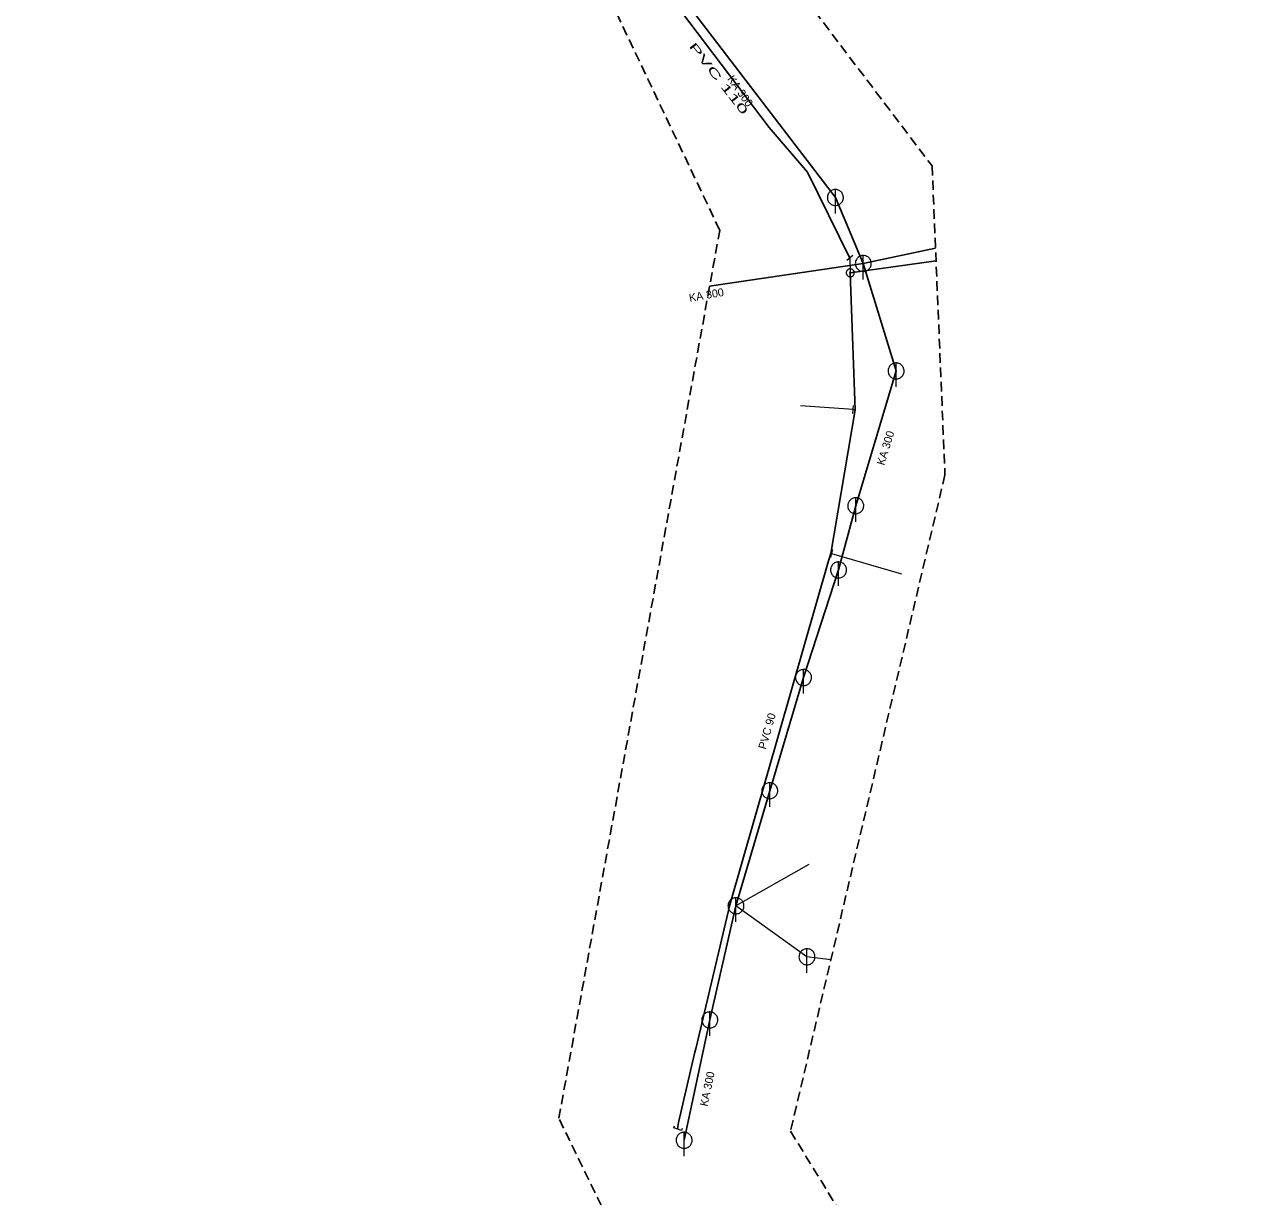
# Model space of a CAD drawing. Extents: x -686636 to -686482, y -972667 to -972167.
# Drawn here: x -686636.4 to -686482.1, y -972450.3 to -972304 of the extents above; entities that cross this region are included whole.
import ezdxf

# ---------------------------------------------------------------- set-up
doc = ezdxf.new("R2010")
doc.units = 0
doc.header["$LTSCALE"] = 0.4
doc.linetypes.add('MEDIUM_DASHED', pattern=[4.5, 3, -1.5])
for name, color, linetype, lineweight in [('1', 7, 'MEDIUM_DASHED', 25), ('11', 7, 'Continuous', 13), ('13', 7, 'Continuous', 13), ('14', 7, 'Continuous', 25), ('17', 7, 'Continuous', 25), ('22', 7, 'Continuous', 13), ('34', 7, 'Continuous', 13), ('47', 7, 'Continuous', 13)]:
    doc.layers.add(name, color=color, linetype=linetype, lineweight=lineweight)

msp = doc.modelspace()

# ---------------------------------------------------------------- linework, layer by layer
at = {"layer": '1'}
msp.add_lwpolyline([(-686523.086, -972200.227), (-686492.539, -972167.269), (-686482.089, -972185.758), (-686542.379, -972270.164), (-686548.006, -972279.81), (-686543.183, -972295.084), (-686523.086, -972321.612), (-686521.478, -972360.197), (-686540.771, -972442.192), (-686521.478, -972473.543), (-686515.047, -972510.521), (-686519.067, -972578.85), (-686529.517, -972667.276), (-686549.614, -972665.668), (-686542.379, -972574.831), (-686589.003, -972562.773), (-686636.432, -972544.284), (-686625.981, -972525.795), (-686541.575, -972549.911), (-686539.967, -972501.678), (-686569.711, -972440.584), (-686549.614, -972329.65), (-686564.887, -972297.496), (-686572.926, -972277.399)], close=True, dxfattribs=at)
at = {"layer": '11'}
msp.add_line((-686538.49, -972408.895), (-686547.583, -972414.038), dxfattribs=at)
msp.add_lwpolyline([(-686535.737, -972420.795), (-686538.713, -972420.403), (-686547.583, -972414.038)], dxfattribs=at)
at = {"layer": '13'}
for p, q in [((-686532.934, -972352.037), (-686539.513, -972351.594)), ((-686535.644, -972370.026), (-686526.917, -972372.571))]:
    msp.add_line(p, q, dxfattribs=at)
at = {"layer": '14'}
for p, q in [((-686554.905, -972299.7), (-686535.172, -972325.548)), ((-686535.172, -972325.548), (-686531.678, -972333.79)), ((-686522.659, -972331.868), (-686531.678, -972333.79)), ((-686531.678, -972333.79), (-686550.876, -972336.617)), ((-686527.584, -972347.218), (-686531.678, -972333.79)), ((-686532.626, -972364.055), (-686527.584, -972347.218)), ((-686534.77, -972372.079), (-686532.626, -972364.055)), ((-686539.147, -972385.523), (-686534.77, -972372.079)), ((-686543.365, -972399.661), (-686539.147, -972385.523)), ((-686547.583, -972414.038), (-686543.365, -972399.661)), ((-686550.85, -972428.295), (-686547.583, -972414.038)), ((-686554.058, -972443.325), (-686550.85, -972428.295))]:
    msp.add_line(p, q, dxfattribs=at)
at = {"layer": '14', "lineweight": 13}
for p, q in [((-686533.358, -972333.116), (-686533.307, -972334.963)), ((-686532.708, -972352.056), (-686532.934, -972352.037)), ((-686535.729, -972370.005), (-686535.644, -972370.026))]:
    msp.add_line(p, q, dxfattribs=at)
at = {"layer": '17'}
msp.add_line((-686533.307, -972334.963), (-686522.593, -972333.453), dxfattribs=at)
for points in [[(-686556.579, -972299.256), (-686556.334, -972299.737), (-686543.419, -972316.782), (-686538.645, -972322.384), (-686533.358, -972333.116)], [(-686533.307, -972334.963), (-686532.708, -972352.056), (-686535.729, -972370.005), (-686536.037, -972370.929), (-686548.355, -972413.919), (-686552.556, -972431.757), (-686552.713, -972432.325), (-686554.769, -972441.1), (-686554.808, -972441.374), (-686554.848, -972441.648), (-686554.867, -972441.942)]]:
    msp.add_lwpolyline(points, dxfattribs=at)
at = {"layer": '22'}
for p, q in [((-686535.172, -972327.548), (-686535.171, -972324.548)), ((-686531.678, -972335.79), (-686531.677, -972332.79)), ((-686527.584, -972349.218), (-686527.583, -972346.218)), ((-686532.626, -972366.055), (-686532.625, -972363.055)), ((-686534.77, -972374.079), (-686534.769, -972371.079)), ((-686539.147, -972387.523), (-686539.146, -972384.523)), ((-686543.365, -972401.661), (-686543.364, -972398.661)), ((-686547.583, -972416.038), (-686547.582, -972413.038)), ((-686538.713, -972422.403), (-686538.712, -972419.403)), ((-686550.85, -972430.295), (-686550.849, -972427.295)), ((-686554.058, -972445.325), (-686554.057, -972442.325))]:
    msp.add_line(p, q, dxfattribs=at)
for points in [[(-686534.172, -972325.548), (-686534.177, -972325.439), (-686534.195, -972325.331), (-686534.225, -972325.225), (-686534.265, -972325.124), (-686534.317, -972325.027), (-686534.379, -972324.937), (-686534.451, -972324.854), (-686534.531, -972324.78), (-686534.619, -972324.714), (-686534.713, -972324.659), (-686534.813, -972324.614), (-686534.918, -972324.581), (-686535.025, -972324.559), (-686535.134, -972324.549), (-686535.244, -972324.551), (-686535.352, -972324.565), (-686535.459, -972324.59), (-686535.562, -972324.627), (-686535.66, -972324.676), (-686535.752, -972324.734), (-686535.838, -972324.803), (-686535.915, -972324.88), (-686535.984, -972324.966), (-686536.043, -972325.058), (-686536.091, -972325.156), (-686536.128, -972325.259), (-686536.154, -972325.366), (-686536.168, -972325.474), (-686536.171, -972325.584), (-686536.161, -972325.693), (-686536.14, -972325.8), (-686536.106, -972325.904), (-686536.062, -972326.004), (-686536.007, -972326.099), (-686535.941, -972326.187), (-686535.867, -972326.267), (-686535.784, -972326.339), (-686535.694, -972326.401), (-686535.598, -972326.453), (-686535.496, -972326.494), (-686535.391, -972326.524), (-686535.283, -972326.542), (-686535.173, -972326.548), (-686535.064, -972326.542), (-686534.956, -972326.524), (-686534.851, -972326.495), (-686534.749, -972326.454), (-686534.652, -972326.402), (-686534.562, -972326.34), (-686534.479, -972326.269), (-686534.404, -972326.189), (-686534.339, -972326.101), (-686534.283, -972326.007), (-686534.239, -972325.907), (-686534.205, -972325.803), (-686534.183, -972325.695), (-686534.173, -972325.586)], [(-686530.678, -972333.79), (-686530.683, -972333.681), (-686530.701, -972333.573), (-686530.731, -972333.467), (-686530.771, -972333.366), (-686530.823, -972333.269), (-686530.885, -972333.179), (-686530.957, -972333.096), (-686531.037, -972333.022), (-686531.125, -972332.956), (-686531.219, -972332.901), (-686531.319, -972332.856), (-686531.424, -972332.823), (-686531.531, -972332.801), (-686531.64, -972332.791), (-686531.75, -972332.793), (-686531.858, -972332.807), (-686531.965, -972332.832), (-686532.068, -972332.869), (-686532.166, -972332.918), (-686532.258, -972332.976), (-686532.344, -972333.045), (-686532.421, -972333.122), (-686532.49, -972333.208), (-686532.549, -972333.3), (-686532.597, -972333.398), (-686532.634, -972333.501), (-686532.66, -972333.608), (-686532.674, -972333.716), (-686532.677, -972333.826), (-686532.667, -972333.935), (-686532.646, -972334.042), (-686532.612, -972334.146), (-686532.568, -972334.246), (-686532.513, -972334.341), (-686532.447, -972334.429), (-686532.373, -972334.509), (-686532.29, -972334.581), (-686532.2, -972334.643), (-686532.104, -972334.695), (-686532.002, -972334.736), (-686531.897, -972334.766), (-686531.789, -972334.784), (-686531.679, -972334.79), (-686531.57, -972334.784), (-686531.462, -972334.766), (-686531.357, -972334.737), (-686531.255, -972334.696), (-686531.158, -972334.644), (-686531.068, -972334.582), (-686530.985, -972334.511), (-686530.91, -972334.431), (-686530.845, -972334.343), (-686530.789, -972334.249), (-686530.745, -972334.149), (-686530.711, -972334.045), (-686530.689, -972333.937), (-686530.679, -972333.828)], [(-686526.584, -972347.218), (-686526.589, -972347.109), (-686526.607, -972347.001), (-686526.637, -972346.895), (-686526.677, -972346.794), (-686526.729, -972346.697), (-686526.791, -972346.607), (-686526.863, -972346.524), (-686526.943, -972346.45), (-686527.031, -972346.384), (-686527.125, -972346.329), (-686527.225, -972346.284), (-686527.33, -972346.251), (-686527.437, -972346.229), (-686527.546, -972346.219), (-686527.656, -972346.221), (-686527.764, -972346.235), (-686527.871, -972346.26), (-686527.974, -972346.297), (-686528.072, -972346.346), (-686528.164, -972346.404), (-686528.25, -972346.473), (-686528.327, -972346.55), (-686528.396, -972346.636), (-686528.455, -972346.728), (-686528.503, -972346.826), (-686528.54, -972346.929), (-686528.566, -972347.036), (-686528.58, -972347.144), (-686528.583, -972347.254), (-686528.573, -972347.363), (-686528.552, -972347.47), (-686528.518, -972347.574), (-686528.474, -972347.674), (-686528.419, -972347.769), (-686528.353, -972347.857), (-686528.279, -972347.937), (-686528.196, -972348.009), (-686528.106, -972348.071), (-686528.01, -972348.123), (-686527.908, -972348.164), (-686527.803, -972348.194), (-686527.695, -972348.212), (-686527.585, -972348.218), (-686527.476, -972348.212), (-686527.368, -972348.194), (-686527.263, -972348.165), (-686527.161, -972348.124), (-686527.064, -972348.072), (-686526.974, -972348.01), (-686526.891, -972347.939), (-686526.816, -972347.859), (-686526.751, -972347.771), (-686526.695, -972347.677), (-686526.651, -972347.577), (-686526.617, -972347.473), (-686526.595, -972347.365), (-686526.585, -972347.256)], [(-686531.626, -972364.055), (-686531.631, -972363.946), (-686531.649, -972363.838), (-686531.679, -972363.732), (-686531.719, -972363.631), (-686531.771, -972363.534), (-686531.833, -972363.444), (-686531.905, -972363.361), (-686531.985, -972363.287), (-686532.073, -972363.221), (-686532.167, -972363.166), (-686532.267, -972363.121), (-686532.372, -972363.088), (-686532.479, -972363.066), (-686532.588, -972363.056), (-686532.698, -972363.058), (-686532.806, -972363.072), (-686532.913, -972363.097), (-686533.016, -972363.134), (-686533.114, -972363.183), (-686533.206, -972363.241), (-686533.292, -972363.31), (-686533.369, -972363.387), (-686533.438, -972363.473), (-686533.497, -972363.565), (-686533.545, -972363.663), (-686533.582, -972363.766), (-686533.608, -972363.873), (-686533.622, -972363.981), (-686533.625, -972364.091), (-686533.615, -972364.2), (-686533.594, -972364.307), (-686533.56, -972364.411), (-686533.516, -972364.511), (-686533.461, -972364.606), (-686533.395, -972364.694), (-686533.321, -972364.774), (-686533.238, -972364.846), (-686533.148, -972364.908), (-686533.052, -972364.96), (-686532.95, -972365.001), (-686532.845, -972365.031), (-686532.737, -972365.049), (-686532.627, -972365.055), (-686532.518, -972365.049), (-686532.41, -972365.031), (-686532.305, -972365.002), (-686532.203, -972364.961), (-686532.106, -972364.909), (-686532.016, -972364.847), (-686531.933, -972364.776), (-686531.858, -972364.696), (-686531.793, -972364.608), (-686531.737, -972364.514), (-686531.693, -972364.414), (-686531.659, -972364.31), (-686531.637, -972364.202), (-686531.627, -972364.093)], [(-686533.77, -972372.079), (-686533.775, -972371.97), (-686533.793, -972371.862), (-686533.823, -972371.756), (-686533.863, -972371.655), (-686533.915, -972371.558), (-686533.977, -972371.468), (-686534.049, -972371.385), (-686534.129, -972371.311), (-686534.217, -972371.245), (-686534.311, -972371.19), (-686534.411, -972371.145), (-686534.516, -972371.112), (-686534.623, -972371.09), (-686534.732, -972371.08), (-686534.842, -972371.082), (-686534.95, -972371.096), (-686535.057, -972371.121), (-686535.16, -972371.158), (-686535.258, -972371.207), (-686535.35, -972371.265), (-686535.436, -972371.334), (-686535.513, -972371.411), (-686535.582, -972371.497), (-686535.641, -972371.589), (-686535.689, -972371.687), (-686535.726, -972371.79), (-686535.752, -972371.897), (-686535.766, -972372.005), (-686535.769, -972372.115), (-686535.759, -972372.224), (-686535.738, -972372.331), (-686535.704, -972372.435), (-686535.66, -972372.535), (-686535.605, -972372.63), (-686535.539, -972372.718), (-686535.465, -972372.798), (-686535.382, -972372.87), (-686535.292, -972372.932), (-686535.196, -972372.984), (-686535.094, -972373.025), (-686534.989, -972373.055), (-686534.881, -972373.073), (-686534.771, -972373.079), (-686534.662, -972373.073), (-686534.554, -972373.055), (-686534.449, -972373.026), (-686534.347, -972372.985), (-686534.25, -972372.933), (-686534.16, -972372.871), (-686534.077, -972372.8), (-686534.002, -972372.72), (-686533.937, -972372.632), (-686533.881, -972372.538), (-686533.837, -972372.438), (-686533.803, -972372.334), (-686533.781, -972372.226), (-686533.771, -972372.117)], [(-686538.147, -972385.523), (-686538.152, -972385.414), (-686538.17, -972385.306), (-686538.2, -972385.2), (-686538.24, -972385.099), (-686538.292, -972385.002), (-686538.354, -972384.912), (-686538.426, -972384.829), (-686538.506, -972384.755), (-686538.594, -972384.689), (-686538.688, -972384.634), (-686538.788, -972384.589), (-686538.893, -972384.556), (-686539, -972384.534), (-686539.109, -972384.524), (-686539.219, -972384.526), (-686539.327, -972384.54), (-686539.434, -972384.565), (-686539.537, -972384.602), (-686539.635, -972384.651), (-686539.727, -972384.709), (-686539.813, -972384.778), (-686539.89, -972384.855), (-686539.959, -972384.941), (-686540.018, -972385.033), (-686540.066, -972385.131), (-686540.103, -972385.234), (-686540.129, -972385.341), (-686540.143, -972385.449), (-686540.146, -972385.559), (-686540.136, -972385.668), (-686540.115, -972385.775), (-686540.081, -972385.879), (-686540.037, -972385.979), (-686539.982, -972386.074), (-686539.916, -972386.162), (-686539.842, -972386.242), (-686539.759, -972386.314), (-686539.669, -972386.376), (-686539.573, -972386.428), (-686539.471, -972386.469), (-686539.366, -972386.499), (-686539.258, -972386.517), (-686539.148, -972386.523), (-686539.039, -972386.517), (-686538.931, -972386.499), (-686538.826, -972386.47), (-686538.724, -972386.429), (-686538.627, -972386.377), (-686538.537, -972386.315), (-686538.454, -972386.244), (-686538.379, -972386.164), (-686538.314, -972386.076), (-686538.258, -972385.982), (-686538.214, -972385.882), (-686538.18, -972385.778), (-686538.158, -972385.67), (-686538.148, -972385.561)], [(-686542.365, -972399.661), (-686542.37, -972399.552), (-686542.388, -972399.444), (-686542.418, -972399.338), (-686542.458, -972399.237), (-686542.51, -972399.14), (-686542.572, -972399.05), (-686542.644, -972398.967), (-686542.724, -972398.893), (-686542.812, -972398.827), (-686542.906, -972398.772), (-686543.006, -972398.727), (-686543.111, -972398.694), (-686543.218, -972398.672), (-686543.327, -972398.662), (-686543.437, -972398.664), (-686543.545, -972398.678), (-686543.652, -972398.703), (-686543.755, -972398.74), (-686543.853, -972398.789), (-686543.945, -972398.847), (-686544.031, -972398.916), (-686544.108, -972398.993), (-686544.177, -972399.079), (-686544.236, -972399.171), (-686544.284, -972399.269), (-686544.321, -972399.372), (-686544.347, -972399.479), (-686544.361, -972399.587), (-686544.364, -972399.697), (-686544.354, -972399.806), (-686544.333, -972399.913), (-686544.299, -972400.017), (-686544.255, -972400.117), (-686544.2, -972400.212), (-686544.134, -972400.3), (-686544.06, -972400.38), (-686543.977, -972400.452), (-686543.887, -972400.514), (-686543.791, -972400.566), (-686543.689, -972400.607), (-686543.584, -972400.637), (-686543.476, -972400.655), (-686543.366, -972400.661), (-686543.257, -972400.655), (-686543.149, -972400.637), (-686543.044, -972400.608), (-686542.942, -972400.567), (-686542.845, -972400.515), (-686542.755, -972400.453), (-686542.672, -972400.382), (-686542.597, -972400.302), (-686542.532, -972400.214), (-686542.476, -972400.12), (-686542.432, -972400.02), (-686542.398, -972399.916), (-686542.376, -972399.808), (-686542.366, -972399.699)], [(-686546.583, -972414.038), (-686546.588, -972413.929), (-686546.606, -972413.821), (-686546.636, -972413.715), (-686546.676, -972413.614), (-686546.728, -972413.517), (-686546.79, -972413.427), (-686546.862, -972413.344), (-686546.942, -972413.27), (-686547.03, -972413.204), (-686547.124, -972413.149), (-686547.224, -972413.104), (-686547.329, -972413.071), (-686547.436, -972413.049), (-686547.545, -972413.039), (-686547.655, -972413.041), (-686547.763, -972413.055), (-686547.87, -972413.08), (-686547.973, -972413.117), (-686548.071, -972413.166), (-686548.163, -972413.224), (-686548.249, -972413.293), (-686548.326, -972413.37), (-686548.395, -972413.456), (-686548.454, -972413.548), (-686548.502, -972413.646), (-686548.539, -972413.749), (-686548.565, -972413.856), (-686548.579, -972413.964), (-686548.582, -972414.074), (-686548.572, -972414.183), (-686548.551, -972414.29), (-686548.517, -972414.394), (-686548.473, -972414.494), (-686548.418, -972414.589), (-686548.352, -972414.677), (-686548.278, -972414.757), (-686548.195, -972414.829), (-686548.105, -972414.891), (-686548.009, -972414.943), (-686547.907, -972414.984), (-686547.802, -972415.014), (-686547.694, -972415.032), (-686547.584, -972415.038), (-686547.475, -972415.032), (-686547.367, -972415.014), (-686547.262, -972414.985), (-686547.16, -972414.944), (-686547.063, -972414.892), (-686546.973, -972414.83), (-686546.89, -972414.759), (-686546.815, -972414.679), (-686546.75, -972414.591), (-686546.694, -972414.497), (-686546.65, -972414.397), (-686546.616, -972414.293), (-686546.594, -972414.185), (-686546.584, -972414.076)], [(-686537.713, -972420.403), (-686537.718, -972420.294), (-686537.736, -972420.186), (-686537.766, -972420.08), (-686537.806, -972419.979), (-686537.858, -972419.882), (-686537.92, -972419.792), (-686537.992, -972419.709), (-686538.072, -972419.635), (-686538.16, -972419.569), (-686538.254, -972419.514), (-686538.354, -972419.469), (-686538.459, -972419.436), (-686538.566, -972419.414), (-686538.675, -972419.404), (-686538.785, -972419.406), (-686538.893, -972419.42), (-686539, -972419.445), (-686539.103, -972419.482), (-686539.201, -972419.531), (-686539.293, -972419.589), (-686539.379, -972419.658), (-686539.456, -972419.735), (-686539.525, -972419.821), (-686539.584, -972419.913), (-686539.632, -972420.011), (-686539.669, -972420.114), (-686539.695, -972420.221), (-686539.709, -972420.329), (-686539.712, -972420.439), (-686539.702, -972420.548), (-686539.681, -972420.655), (-686539.647, -972420.759), (-686539.603, -972420.859), (-686539.548, -972420.954), (-686539.482, -972421.042), (-686539.408, -972421.122), (-686539.325, -972421.194), (-686539.235, -972421.256), (-686539.139, -972421.308), (-686539.037, -972421.349), (-686538.932, -972421.379), (-686538.824, -972421.397), (-686538.714, -972421.403), (-686538.605, -972421.397), (-686538.497, -972421.379), (-686538.392, -972421.35), (-686538.29, -972421.309), (-686538.193, -972421.257), (-686538.103, -972421.195), (-686538.02, -972421.124), (-686537.945, -972421.044), (-686537.88, -972420.956), (-686537.824, -972420.862), (-686537.78, -972420.762), (-686537.746, -972420.658), (-686537.724, -972420.55), (-686537.714, -972420.441)], [(-686549.85, -972428.295), (-686549.855, -972428.186), (-686549.873, -972428.078), (-686549.903, -972427.972), (-686549.943, -972427.871), (-686549.995, -972427.774), (-686550.057, -972427.684), (-686550.129, -972427.601), (-686550.209, -972427.527), (-686550.297, -972427.461), (-686550.391, -972427.406), (-686550.491, -972427.361), (-686550.596, -972427.328), (-686550.703, -972427.306), (-686550.812, -972427.296), (-686550.922, -972427.298), (-686551.03, -972427.312), (-686551.137, -972427.337), (-686551.24, -972427.374), (-686551.338, -972427.423), (-686551.43, -972427.481), (-686551.516, -972427.55), (-686551.593, -972427.627), (-686551.662, -972427.713), (-686551.721, -972427.805), (-686551.769, -972427.903), (-686551.806, -972428.006), (-686551.832, -972428.113), (-686551.846, -972428.221), (-686551.849, -972428.331), (-686551.839, -972428.44), (-686551.818, -972428.547), (-686551.784, -972428.651), (-686551.74, -972428.751), (-686551.685, -972428.846), (-686551.619, -972428.934), (-686551.545, -972429.014), (-686551.462, -972429.086), (-686551.372, -972429.148), (-686551.276, -972429.2), (-686551.174, -972429.241), (-686551.069, -972429.271), (-686550.961, -972429.289), (-686550.851, -972429.295), (-686550.742, -972429.289), (-686550.634, -972429.271), (-686550.529, -972429.242), (-686550.427, -972429.201), (-686550.33, -972429.149), (-686550.24, -972429.087), (-686550.157, -972429.016), (-686550.082, -972428.936), (-686550.017, -972428.848), (-686549.961, -972428.754), (-686549.917, -972428.654), (-686549.883, -972428.55), (-686549.861, -972428.442), (-686549.851, -972428.333)], [(-686553.058, -972443.325), (-686553.063, -972443.216), (-686553.081, -972443.108), (-686553.111, -972443.002), (-686553.151, -972442.901), (-686553.203, -972442.804), (-686553.265, -972442.714), (-686553.337, -972442.631), (-686553.417, -972442.557), (-686553.505, -972442.491), (-686553.599, -972442.436), (-686553.699, -972442.391), (-686553.804, -972442.358), (-686553.911, -972442.336), (-686554.02, -972442.326), (-686554.13, -972442.328), (-686554.238, -972442.342), (-686554.345, -972442.367), (-686554.448, -972442.404), (-686554.546, -972442.453), (-686554.638, -972442.511), (-686554.724, -972442.58), (-686554.801, -972442.657), (-686554.87, -972442.743), (-686554.929, -972442.835), (-686554.977, -972442.933), (-686555.014, -972443.036), (-686555.04, -972443.143), (-686555.054, -972443.251), (-686555.057, -972443.361), (-686555.047, -972443.47), (-686555.026, -972443.577), (-686554.992, -972443.681), (-686554.948, -972443.781), (-686554.893, -972443.876), (-686554.827, -972443.964), (-686554.753, -972444.044), (-686554.67, -972444.116), (-686554.58, -972444.178), (-686554.484, -972444.23), (-686554.382, -972444.271), (-686554.277, -972444.301), (-686554.169, -972444.319), (-686554.059, -972444.325), (-686553.95, -972444.319), (-686553.842, -972444.301), (-686553.737, -972444.272), (-686553.635, -972444.231), (-686553.538, -972444.179), (-686553.448, -972444.117), (-686553.365, -972444.046), (-686553.29, -972443.966), (-686553.225, -972443.878), (-686553.169, -972443.784), (-686553.125, -972443.684), (-686553.091, -972443.58), (-686553.069, -972443.472), (-686553.059, -972443.363)]]:
    msp.add_lwpolyline(points, close=True, dxfattribs=at)
at = {"layer": '34'}
for p, q in [((-686532.975, -972332.793), (-686533.741, -972333.437)), ((-686532.975, -972352.535), (-686532.891, -972351.538)), ((-686535.525, -972369.54), (-686535.763, -972370.511))]:
    msp.add_line(p, q, dxfattribs=at)
at = {"layer": '47'}
for points in [[(-686532.811, -972334.893), (-686532.822, -972334.842), (-686532.837, -972334.791), (-686532.858, -972334.744), (-686532.882, -972334.698), (-686532.913, -972334.654), (-686532.948, -972334.615), (-686532.986, -972334.58), (-686533.028, -972334.549), (-686533.072, -972334.521), (-686533.119, -972334.499), (-686533.169, -972334.482), (-686533.22, -972334.471), (-686533.272, -972334.464), (-686533.324, -972334.463), (-686533.376, -972334.467), (-686533.427, -972334.478), (-686533.478, -972334.493), (-686533.526, -972334.514), (-686533.571, -972334.538), (-686533.615, -972334.569), (-686533.654, -972334.604), (-686533.69, -972334.642), (-686533.721, -972334.684), (-686533.749, -972334.728), (-686533.77, -972334.775), (-686533.787, -972334.825), (-686533.799, -972334.876), (-686533.805, -972334.928), (-686533.806, -972334.98), (-686533.802, -972335.032), (-686533.791, -972335.083), (-686533.776, -972335.134), (-686533.756, -972335.182), (-686533.731, -972335.227), (-686533.7, -972335.271), (-686533.666, -972335.31), (-686533.628, -972335.346), (-686533.586, -972335.378), (-686533.541, -972335.405), (-686533.494, -972335.426), (-686533.444, -972335.443), (-686533.394, -972335.455), (-686533.341, -972335.461), (-686533.289, -972335.462), (-686533.237, -972335.458), (-686533.186, -972335.447), (-686533.135, -972335.432), (-686533.088, -972335.412), (-686533.042, -972335.387), (-686532.998, -972335.356), (-686532.959, -972335.322), (-686532.924, -972335.284), (-686532.892, -972335.242), (-686532.865, -972335.197), (-686532.843, -972335.15), (-686532.826, -972335.1), (-686532.815, -972335.05), (-686532.808, -972334.997), (-686532.807, -972334.945)], [(-686533.225, -972334.951), (-686533.227, -972334.942), (-686533.23, -972334.934), (-686533.233, -972334.927), (-686533.237, -972334.919), (-686533.242, -972334.912), (-686533.248, -972334.906), (-686533.254, -972334.9), (-686533.261, -972334.894), (-686533.268, -972334.89), (-686533.276, -972334.886), (-686533.284, -972334.884), (-686533.293, -972334.882), (-686533.301, -972334.881), (-686533.309, -972334.88), (-686533.318, -972334.881), (-686533.327, -972334.883), (-686533.335, -972334.886), (-686533.342, -972334.889), (-686533.35, -972334.893), (-686533.357, -972334.898), (-686533.363, -972334.904), (-686533.369, -972334.91), (-686533.375, -972334.917), (-686533.38, -972334.924), (-686533.383, -972334.932), (-686533.385, -972334.94), (-686533.387, -972334.949), (-686533.388, -972334.957), (-686533.389, -972334.965), (-686533.388, -972334.974), (-686533.386, -972334.983), (-686533.383, -972334.991), (-686533.38, -972334.998), (-686533.376, -972335.006), (-686533.371, -972335.013), (-686533.366, -972335.019), (-686533.359, -972335.025), (-686533.352, -972335.031), (-686533.345, -972335.036), (-686533.337, -972335.039), (-686533.329, -972335.041), (-686533.32, -972335.043), (-686533.312, -972335.044), (-686533.304, -972335.045), (-686533.295, -972335.044), (-686533.286, -972335.042), (-686533.278, -972335.039), (-686533.271, -972335.036), (-686533.263, -972335.032), (-686533.256, -972335.027), (-686533.25, -972335.022), (-686533.244, -972335.015), (-686533.238, -972335.008), (-686533.234, -972335.001), (-686533.23, -972334.993), (-686533.228, -972334.985), (-686533.226, -972334.976), (-686533.225, -972334.968), (-686533.224, -972334.96)]]:
    msp.add_lwpolyline(points, close=True, dxfattribs=at)
msp.add_lwpolyline([(-686554.314, -972441.875), (-686554.401, -972442.112), (-686555.332, -972441.771), (-686555.246, -972441.534)], dxfattribs=at)

# ---------------------------------------------------------------- texts
at = {"layer": '1', "width": 2.05}
msp.add_text('PVC 110 ', height=1, rotation=308, dxfattribs=at).set_placement((-686553.518, -972306.661))
at = {"layer": '1'}
for s, rotation, p in [('KA 300', 305, (-686548.71, -972310.739)), ('KA 300', 10, (-686553.355, -972338.592)), ('KA 300', 73, (-686529.063, -972359.08)), ('PVC 90', 74, (-686543.856, -972394.561)), ('KA 300', 78, (-686551.138, -972439.158))]:
    msp.add_text(s, height=1, rotation=rotation, dxfattribs=at).set_placement(p)

doc.saveas('drawing.dxf')
